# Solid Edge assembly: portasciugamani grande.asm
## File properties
Title: P.Asciugamani
Author: i.fialdini
Template: iso assembly.asm
Last saved by: a.ravenna
Revision: 16
Application: Solid Edge
Tipo di contenuto documento: 1
Document Number: 6008
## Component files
portasciugamani grande.par
portasciugamani grande_0.par
portasciugamani grande_1.par
portasciugamani grande_2.par
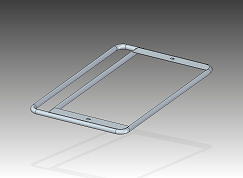
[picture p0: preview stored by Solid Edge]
